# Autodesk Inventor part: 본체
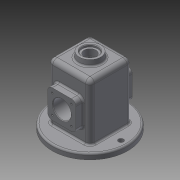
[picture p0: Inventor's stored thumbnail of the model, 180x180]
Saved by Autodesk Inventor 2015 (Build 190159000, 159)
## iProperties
Created: 2021-08
Part Number: 본체
Material: 일반
Document SubType Name: Modeling
Designer: 10401
Density: 1 g/cm^3
Appearance: 기본값
Author: 10401
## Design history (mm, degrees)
sketch "스케치1"
  geometry: L1 (-37, 37)-(37, 37); L2 (37, 37)-(37, -37); L3 (37, -37)-(-37, -37); L4 (-37, -37)-(-37, 37); L5 (-37, 37)-(37, -37); L6 (37, 37)-(-37, -37); 1 further point
  constraints: 12 end point, 2 midpoint, 2 parallel, 1 horizontal, 1 perpendicular
  dimensions: "d1" = 74 distance of L1.end L2.end; "d2" = 74 distance of L2.end L3.end
extrude "돌출1" new body sketch "스케치1" distance "d3" = 110; taper "d4" = 0 deg
fillet "모깎기1" dims "d5" = 8
fillet "모깎기2" dims "d6" = 8
feature "쉘1" dims "d7" = 5
sketch "스케치2"
  geometry: L1 (-29, 32)-(29, 32) reference; L2 (32, 29)-(32, -29) reference; L3 (29, -32)-(-29, -32) reference; L4 (-32, -29)-(-32, 29) reference; L5 (-29, -37)-(29, -37) reference; L6 (37, -29)-(37, 29) reference; L7 (29, 37)-(-29, 37) reference; L8 (-37, 29)-(-37, -29) reference; C1 r 67 at (0, 0); A1 r 3 centre (-29, 29) between (-29, 32) and (-32, 29) reference; A2 r 3 centre (29, 29) between (32, 29) and (29, 32) reference; A3 r 3 centre (29, -29) between (29, -32) and (32, -29) reference; A4 r 3 centre (-29, -29) between (-32, -29) and (-29, -32) reference; A5 r 8 centre (-29, -29) between (-37, -29) and (-29, -37) reference; A6 r 8 centre (29, -29) between (29, -37) and (37, -29) reference; A7 r 8 centre (29, 29) between (37, 29) and (29, 37) reference; A8 r 8 centre (-29, 29) between (-29, 37) and (-37, 29) reference; 1 further point
  constraints: 1 centre point, 1 coincident
  dimensions: "d68" = 134 diameter of C1
extrude "돌출2" join sketch "스케치2" distance "d8" = 10; taper "d9" = 0 deg
sketch "스케치3"
  geometry: C1 r 20 at (0, 0); 1 further point
  constraints: 1 centre point, 1 coincident
  dimensions: "d10" = 40 diameter of C1
extrude "돌출3" join sketch "스케치3" distance "d11" = 10; taper "d12" = 0 deg
sketch "스케치4"
  geometry: L1 (4, -72)-(54, -72); L2 (54, -72)-(54, -22); L3 (54, -22)-(4, -22); L4 (4, -22)-(4, -72); L5 (4, -72)-(54, -22); L6 (54, -72)-(4, -22); L7 (96, -102)-(-38, -102) reference; 3 further points
  constraints: 12 end point, 3 midpoint, 2 parallel, 1 horizontal, 1 perpendicular, 1 vertical alignment
  dimensions: "d13" = 50 distance of L2.end L3.end; "d14" = 50 distance of L1.end L2.end; "d15" = 55 distance from line of point (29, -47) L7
extrude "돌출4" join sketch "스케치4" distance "d16" = 13; taper "d18" = 0 deg; dims "d17" = 12, "d19" = 0
fillet "모깎기3" dims "d20" = 8
fillet "모깎기4" dims "d21" = 8
fillet "모깎기5" dims "d22" = 25
fillet "모깎기6" dims "d23" = 25
feature "면 기울기1" dims angle "d24" = 20 deg
feature "면 기울기2" dims angle "d25" = 20 deg
sketch "스케치5"
  geometry: C1 r 22.452 at (29, -47) reference; C2 r 16 at (29, -47); 1 further point
  constraints: 1 centre point, 1 coincident
  dimensions: "d26" = 32 diameter of C2
extrude "돌출5" cut sketch "스케치5" stored distance "d27" = 13; taper "d28" = 0 deg
sketch "스케치6"
  geometry: L1 (54, -64)-(54, -30) reference; L2 (46, -22)-(12, -22) reference; L3 (4, -30)-(4, -64) reference; L4 (12, -72)-(46, -72) reference; C1 r 16 at (29, -47) reference; A1 r 8 centre (46, -64) between (46, -72) and (54, -64) reference; A2 r 8 centre (46, -30) between (54, -30) and (46, -22) reference; A3 r 8 centre (12, -30) between (12, -22) and (4, -30) reference; A4 r 8 centre (12, -64) between (4, -64) and (12, -72) reference; 1 further point
hole "구멍1" sketch "스케치6" at (12, -30), (46, -30), (46, -64), (12, -64) diameter "d29" = 3.242; stored, may be unused: countersink angle "d33" = 90 deg, drill point angle "d35" = 118 deg; dims "d30" = 8, "d31" = 4, "d32" = 2, "d34" = 10
sketch "스케치7"
  geometry: A1 r 55 centre (0, 0) between (0, 55) and (-55, 0); 3 further points
  constraints: 4 point on circle, 1 centre point, 1 coincident
  dimensions: "d36" = 110 diameter of A1
hole "구멍2" sketch "스케치7" at (-55, 0), (55, 0) diameter "d37" = 9; stored, may be unused: countersink angle "d41" = 90 deg, drill point angle "d43" = 118 deg; dims "d38" = 8, "d39" = 4, "d40" = 2, "d42" = 10
fillet "모깎기7" dims "d44" = 3
sketch "스케치8"
  geometry: 1 further point
hole "구멍3" sketch "스케치8" at (0, 0) diameter "d45" = 21; stored, may be unused: countersink angle "d49" = 90 deg, drill point angle "d51" = 118 deg; dims "d46" = 8, "d47" = 28, "d48" = 4, "d50" = 10
fillet "모깎기8" dims "d52" = 3
fillet "모깎기9" dims "d53" = 3
chamfer "모따기1" distance "d54" = 1; stored, may be unused: second distance "d55" = 2, angle "d56" = 45 deg
sketch "스케치9"
  geometry: L1 (49, 18)-(9, 18) reference; L2 (-8, 0)-(-8, -89) reference; 2 further points
  constraints: 1 other
  dimensions: "d57" = 28 distance from line of point (29, -10) L1; "d58" = 37 distance from line of L2 point (29, -10)
feature "엠보싱1" sketch "스케치9" dims "d1" = 74, "d2" = 74, "d59" = 0.5, "d60" = 0
sketch "스케치10"
  geometry: L1 (42, -8)-(42, -42) reference; L2 (0, 0)-(34, 0) reference; L3 (-8, -42)-(-8, -8) reference; L4 (34, -50)-(0, -50) reference; C1 r 17 at (17, -25) reference; A1 r 8 centre (34, -42) between (34, -50) and (42, -42) reference; A2 r 8 centre (34, -8) between (42, -8) and (34, 0) reference; A3 r 8 centre (0, -8) between (0, 0) and (-8, -8) reference; A4 r 8 centre (0, -42) between (-8, -42) and (0, -50) reference; 1 further point
hole "구멍4" sketch "스케치10" at (0, -8), (34, -8), (34, -42), (0, -42) diameter "d61" = 3.242; stored, may be unused: countersink angle "d65" = 90 deg, drill point angle "d67" = 118 deg; dims "d62" = 8, "d63" = 4, "d64" = 2, "d66" = 10
feature "면 기울기3" dims angle "d69" = 6 deg
fillet "모깎기10" dims "d70" = 3
node "솔리드1"
mirror "대칭1"
node "투영된 루프1"
node "투영된 루프2"
node "투영된 루프3"
